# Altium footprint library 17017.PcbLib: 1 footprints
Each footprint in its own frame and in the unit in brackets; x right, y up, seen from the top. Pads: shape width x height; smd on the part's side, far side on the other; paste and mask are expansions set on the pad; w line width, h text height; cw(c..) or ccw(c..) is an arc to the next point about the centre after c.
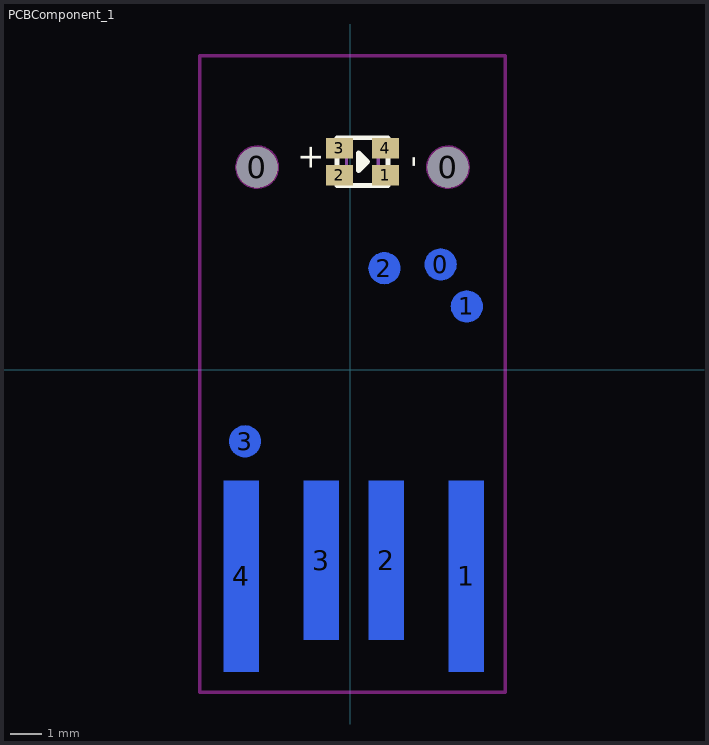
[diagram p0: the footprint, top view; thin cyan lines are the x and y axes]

## PCBComponent_1 [mm]
pads (14):
  round 1.28 hole 1.28: 0(-2.927,6.365) 0(3.073,6.365)
  round 1 smd far side: 0(2.843,3.315) 1(3.663,1.995) 2(1.073,3.195) 3(-3.307,-2.245)
  rect 0.85x0.65 smd paste+0: 1(1.108,6.12) 2(-0.342,6.12) 3(-0.342,6.97) 4(1.108,6.97)
  rect 1.1x6 smd far side: 1(3.642,-6.484) 4(-3.43,-6.484)
  rect 1.1x5 smd far side: 2(1.124,-5.984) 3(-0.918,-5.984)
Top Overlay:
  region: 0.263,6.26 0.543,6.54 0.263,6.82
  lines w0.15: -0.417,5.795 -0.417,7.295 ; 1.183,5.795 1.183,7.295
  lines w0.152: -0.417,5.795 1.183,5.795 ; -0.417,7.295 1.183,7.295 ; 0.263,6.26 0.543,6.54 0.263,6.82 0.263,6.26
  text "-" at 2.283,6.345 h0.76
  text "+" at -0.917,6.245 h0.76
Bottom Overlay:
  region: -1.567,-10.095 -1.567,-2.935 -2.787,-2.935 -2.787,-10.095
  region: 0.513,-10.105 0.513,-2.925 -0.297,-2.925 -0.297,-10.105
  region: 3.053,-10.19 3.053,-2.895 1.743,-2.895 1.743,-10.19
  region: 4.443,-9.545 -4.317,-9.545 -4.317,-10.075 4.443,-10.075
  region: 4.453,-2.905 -4.307,-2.905 -4.307,-3.435 4.453,-3.435
  region: 1.863,-8.535 -1.727,-8.535 -1.727,-9.845 1.863,-9.845
  region: -4.267,-3.395 -4.267,-9.685 -4.027,-9.685 -4.027,-3.395
  region: 4.243,-3.305 4.243,-9.695 4.423,-9.695 4.423,-3.305
  lines w0.152: -4.33,-10.119 4.464,-10.119 4.464,-2.869 -4.33,-2.869 -4.33,-10.119
  text "YJ-17017-USB-UART" at 4.233,7.315 h0.55
Keep-Out Layer:
  circle w0.1: c3.073,6.37 r0.64
  circle w0.1: c-2.927,6.37 r0.64
  lines w0.1: -4.727,-10.13 -4.727,9.87 4.873,9.87 4.873,-10.13 -4.727,-10.13
Mechanical 7:
  lines w0.1: -0.117,5.795 -0.117,7.295 ; 0.883,5.795 0.883,7.295 ; -0.417,5.795 -0.417,7.295 1.183,7.295 1.183,5.795 -0.417,5.795
3D body: height 0.18, standoff 0, extent -0.417,5.795 1.183,7.295
3D body: height 0.55, standoff 0.18, extent -0.167,5.795 0.933,7.295
3D body: height 0.36, standoff 0.18, extent 0.233,5.995 0.533,6.295
3D body: height 0.36, standoff 0.18, extent 0.233,6.795 0.533,7.095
